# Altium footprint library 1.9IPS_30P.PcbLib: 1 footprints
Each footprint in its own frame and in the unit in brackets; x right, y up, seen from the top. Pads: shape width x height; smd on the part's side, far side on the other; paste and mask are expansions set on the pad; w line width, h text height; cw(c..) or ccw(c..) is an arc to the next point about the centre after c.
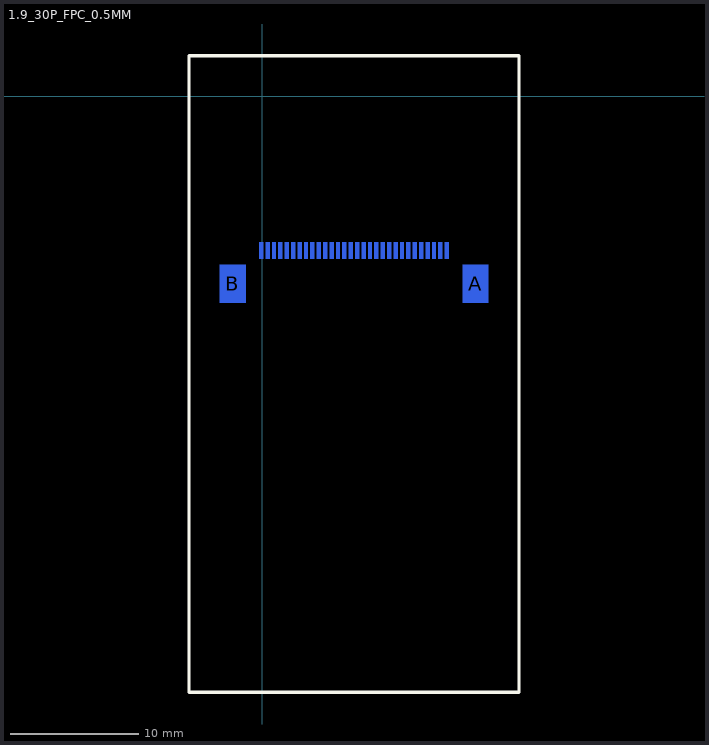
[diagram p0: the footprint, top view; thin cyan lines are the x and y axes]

## 1.9_30P_FPC_0.5MM [mm]
pads (32):
  rect 0.3x1.3 smd far side: 1(14.435,-12.028) 2(13.935,-12.028) 3(13.435,-12.028) 4(12.935,-12.028) 5(12.435,-12.028) 6(11.935,-12.028) 7(11.435,-12.028) 8(10.935,-12.028) 9(10.435,-12.028) 10(9.935,-12.028) 11(9.435,-12.028) 12(8.935,-12.028) 13(8.435,-12.028) 14(7.935,-12.028) 15(7.435,-12.028) 16(6.935,-12.028) 17(6.435,-12.028) 18(5.935,-12.028) 19(5.435,-12.028) 20(4.935,-12.028) 21(4.435,-12.028) 22(3.935,-12.028) 23(3.435,-12.028) 24(2.935,-12.028) 25(2.435,-12.028) 26(1.935,-12.028) 27(1.435,-12.028) 28(0.935,-12.028) 29(0.435,-12.028) 30(-0.065,-12.028)
  rect 2x3 smd far side: A(16.685,-14.63) B(-2.29,-14.63)
Top Overlay:
  lines w0.254: -5.715,-46.545 20.085,-46.545 20.085,3.175 -5.715,3.175 -5.715,-46.545
Bottom Overlay:
  circle w0.356: c15.172,-11.901 r0.178
  lines w0.203: -2.49,-16.346 -2.49,-17.845 16.885,-17.845 16.885,-16.321 ; -2.49,-12.943 -2.49,-12.587 -0.359,-12.587 ; 14.74,-12.595 16.885,-12.595 16.885,-12.943
  text "1" at 16.685,-12.211 h0.89
  text "30" at -0.92,-12.211 h0.89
